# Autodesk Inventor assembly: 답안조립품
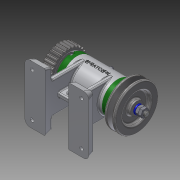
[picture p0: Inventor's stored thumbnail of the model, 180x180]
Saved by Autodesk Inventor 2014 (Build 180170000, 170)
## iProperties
Created: 2016-07
Part Number: 답안조립품
Document SubType Name: Assembly
Designer: USER
Author: USER
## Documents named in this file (16)
- C:\Users\USER\Desktop\460707V1020\답안조립품.iam
- C:\Users\USER\Desktop\460707V1020\460707V1020.ipt
- C:\Users\USER\Desktop\460707V1020\V벨트풀리.ipt
- C:\Users\USER\Desktop\460707V1020\너트 M 8.ipt
- C:\Users\USER\Desktop\460707V1020\니플 M 6 x 0.75.ipt
- C:\Users\USER\Desktop\460707V1020\베어링 15 x 32 x 9.ipt
- C:\Users\USER\Desktop\460707V1020\볼트 M 6 x 8.ipt
- C:\Users\USER\Desktop\460707V1020\볼트 M4 x 12.ipt
- C:\Users\USER\Desktop\460707V1020\스퍼기어.ipt
- C:\Users\USER\Desktop\460707V1020\스프링와셔 8.ipt
- C:\Users\USER\Desktop\460707V1020\오일 실 15 25 7.ipt
- C:\Users\USER\Desktop\460707V1020\와셔 6x11.5.ipt
- C:\Users\USER\Desktop\460707V1020\와셔 8x17.ipt
- C:\Users\USER\Desktop\460707V1020\축.ipt
- C:\Users\USER\Desktop\460707V1020\커버.ipt
- C:\Users\USER\Desktop\460707V1020\키 3 x 3 x 12.ipt
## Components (12 placed, 4 different names)
1. 460707V1020:1 — 플러쉬:1
2. V벨트풀리:1
3. KS B 2023 6002 - 15 x 32 x 9:1
4. KS B 2023 6002 - 15 x 32 x 9:2
5. ISO 4762 M4 x 12:5
6. ISO 4762 M4 x 12:6
7. ISO 4762 M4 x 12:7
8. ISO 4762 M4 x 12:8
9. ISO 4762 M4 x 12:1
10. ISO 4762 M4 x 12:2
11. ISO 4762 M4 x 12:3
12. ISO 4762 M4 x 12:4
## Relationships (1: Flush 1)
- 플러쉬:1 [Flush]: 460707V1020:1
